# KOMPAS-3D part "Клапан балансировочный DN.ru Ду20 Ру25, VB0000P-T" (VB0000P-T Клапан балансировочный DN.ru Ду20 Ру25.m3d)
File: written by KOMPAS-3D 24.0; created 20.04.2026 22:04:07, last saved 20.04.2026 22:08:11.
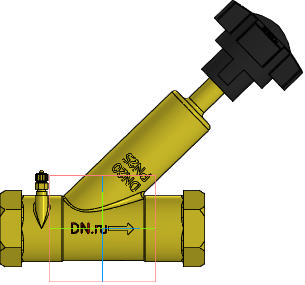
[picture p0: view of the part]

Document properties: Автор: DN.ru; Полное имя файла: E:\Работа\Зайцев\АУТСОРС\Диман\Балансировка\VB0000P-T Клапан балансировочный DN.ru Ду15-50 Ру25\DN20\VB0000P-T Клапан балансировочный DN.ru Ду20 Ру25.m3d

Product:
- Part/product: Клапан балансировочный DN.ru Ду20 Ру25  | designation VB0000P-T
    Масса: 0.58
    Раздел спецификации: Прочие изделия
    Примечание: D080-01176

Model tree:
1. Операция без истории:1

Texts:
  VB0000P-T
